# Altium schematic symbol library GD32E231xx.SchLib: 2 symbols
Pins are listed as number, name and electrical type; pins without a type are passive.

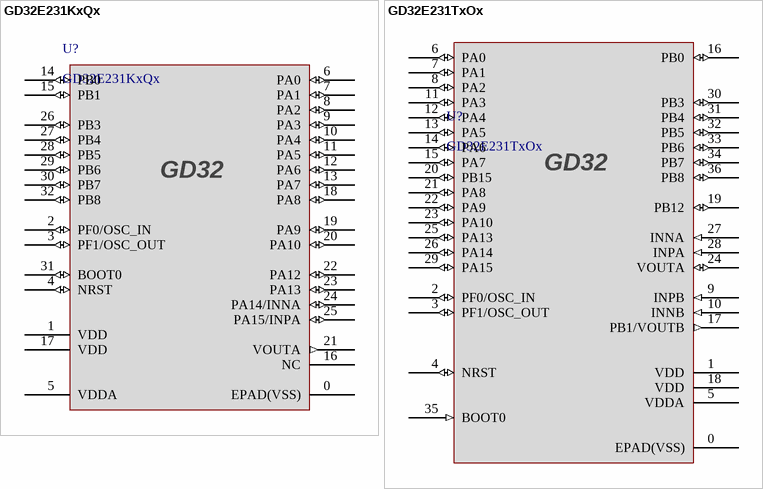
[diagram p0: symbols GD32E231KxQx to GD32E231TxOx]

## GD32E231KxQx
designator U?
footprint QFN32_4x4x0.8
pins: 0 EPAD(VSS) (power), 1 VDD (power), 2 PF0/OSC_IN (io), 3 PF1/OSC_OUT (io), 4 NRST (io), 5 VDDA (power), 6 PA0 (io), 7 PA1 (io), 8 PA2 (io), 9 PA3 (io), 10 PA4 (io), 11 PA5 (io), 12 PA6 (io), 13 PA7 (io), 14 PB0 (io), 15 PB1 (io), 16 NC, 17 VDD (power), 18 PA8 (io), 19 PA9 (io), 20 PA10 (io), 21 VOUTA (out), 22 PA12 (io), 23 PA13 (io), 24 PA14/INNA (io), 25 PA15/INPA (io), 26 PB3 (io), 27 PB4 (io), 28 PB5 (io), 29 PB6 (io), 30 PB7 (io), 31 BOOT0 (io), 32 PB8 (io)

## GD32E231TxOx
designator U?
footprint QFN36_4X4X0.6
pins: 0 EPAD(VSS) (power), 1 VDD (power), 2 PF0/OSC_IN (io), 3 PF1/OSC_OUT (io), 4 NRST (io), 5 VDDA (power), 6 PA0 (io), 7 PA1 (io), 8 PA2 (io), 9 INPB (in), 10 INNB (in), 11 PA3 (io), 12 PA4 (io), 13 PA5 (io), 14 PA6 (io), 15 PA7 (io), 16 PB0 (io), 17 PB1/VOUTB (out), 18 VDD (power), 19 PB12 (io), 20 PB15 (io), 21 PA8 (io), 22 PA9 (io), 23 PA10 (io), 24 VOUTA (io), 25 PA13 (io), 26 PA14 (io), 27 INNA (in), 28 INPA (in), 29 PA15 (io), 30 PB3 (io), 31 PB4 (io), 32 PB5 (io), 33 PB6 (io), 34 PB7 (io), 35 BOOT0 (in), 36 PB8 (io)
